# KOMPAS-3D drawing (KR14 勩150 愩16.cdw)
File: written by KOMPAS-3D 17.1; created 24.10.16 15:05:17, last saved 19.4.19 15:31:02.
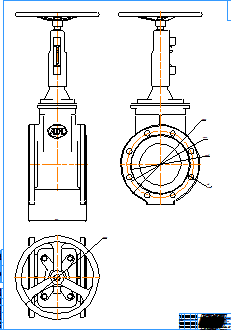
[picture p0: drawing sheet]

Sheet 1: A0, portrait

Title block, sheet 1: name: KR14 Ду150 Ру16; material: Внимание! Данный продукт является объектом авторского права ООО «Торговый Дом АДЛ». / Запрещается изменение, копирование, распространение / (в том числе путем копирования на другие сайты и ресурсы в Интернете) / или любое иное использование информации и объектов без предварительного / согласия правообладателя (ООО «Торговый Дом АДЛ»).; mass: 42; sheets: 1; organisation: ООО "Торговый дом АДЛ"; sheet format: A0; stored path: \\adlc.lan\data\АДЛ_ПКД\3D-модели\ADL production\Клиновые задвижки серии KR ГРАНАР\Клиновые задвижки KR14\kompas 2d\KR14 Ду150 Ру16.cdw

Views: Вид 1
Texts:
  Klimkovich
  ADL
Dimensions and other numbers on the sheet: 210; 1:1; 1; 42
